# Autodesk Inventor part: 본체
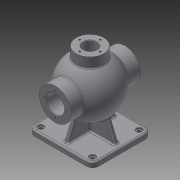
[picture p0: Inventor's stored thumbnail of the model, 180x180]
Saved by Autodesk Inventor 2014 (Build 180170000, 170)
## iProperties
Created: 2015-10
Part Number: 본체
Material: Generic
Document SubType Name: Modeling
Designer: youjin22
Density: 1 g/cm^3
Appearance: Default
Author: youjin22
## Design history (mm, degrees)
sketch "스케치1"
  geometry: L1 (-50.5, 57.5)-(50.5, 57.5); L2 (62.5, 45.5)-(62.5, -45.5); L3 (50.5, -57.5)-(-50.5, -57.5); L4 (-62.5, -45.5)-(-62.5, 45.5); L5 (-62.5, 57.5)-(62.5, -57.5); L6 (62.5, 57.5)-(-62.5, -57.5); A1 r 12 centre (-50.5, 45.5) between (-50.5, 57.5) and (-62.5, 45.5); A2 r 12 centre (50.5, 45.5) between (62.5, 45.5) and (50.5, 57.5); A3 r 12 centre (50.5, -45.5) between (50.5, -57.5) and (62.5, -45.5); A4 r 12 centre (-50.5, -45.5) between (-62.5, -45.5) and (-50.5, -57.5); 1 further point
  constraints: 12 end point, 8 point on circle, 8 point on line, 8 tangent, 4 centre point, 3 equal radius, 2 midpoint, 2 parallel, 1 horizontal, 1 perpendicular
  dimensions: "d0" = 125 distance of L5.end L6.end; "d1" = 115 distance of L6.start L5.end; "d2" = 12 radius of A1
extrude "돌출1" new body sketch "스케치1" distance "d3" = 10; taper "d4" = 0 deg
sketch "스케치2"
  geometry: L1 (0, 32)-(0, 138); A1 r 53 centre (0, 85) between (0, 32) and (0, 138); A2 r 53 centre (0, 85) between (0, 138) and (0, 32); 1 further point
  constraints: 4 point on circle, 2 centre point, 2 end point, 1 vertical, 1 vertical alignment
  dimensions: "d5" = 53 radius of A1; "d6" = 85 distance of A1.centre point (0, 0)
revolve "회전1" stored, may be unused: angle "d7" = 90 deg
sketch "스케치3"
  geometry: L1 (-50.5, 10)-(-62.5, 10) reference; L2 (62.5, 10)-(50.5, 10) reference; L3 (-52.5, 10)-(-37.379, 47.426); L4 (52.5, 10)-(37.379, 47.426); L5 (-62.5, 0)-(-62.5, 10) reference; L6 (62.5, 0)-(62.5, 10) reference; L7 (-52.5, 10)-(52.5, 10); L8 (-37.379, 47.426)-(37.379, 47.426); A1 r 53 centre (0, 85) between (-37.379, 47.426) and (37.379, 47.426) reference; 1 further point
  constraints: 8 end point, 2 point on circle, 2 point on line, 1 perpendicular
  dimensions: "d8" = 10 distance of L3.start L1.end; "d9" = 10 distance of L4.start L2.start; "d10" = 22 deg angle of L3 L5; "d11" = 22 deg angle of L4 L6
extrude "돌출2" join sketch "스케치3" stored distance "d12" = 8; taper "d13" = 0 deg
extrude "돌출10" join sketch "스케치3" stored distance "d96" = 8; taper "d97" = 0 deg
sketch "스케치4"
  geometry: L1 (-45.5, 10)-(-57.5, 10) reference; L2 (57.5, 10)-(45.5, 10) reference; L3 (-47.5, 10)-(-33.719, 44.109); L4 (47.5, 10)-(33.719, 44.109); L5 (57.5, 0)-(57.5, 10) reference; L6 (-57.5, 0)-(-57.5, 10) reference; L7 (-33.719, 44.109)-(33.719, 44.109); A1 r 53 centre (0, 85) between (-33.719, 44.109) and (33.719, 44.109) reference; 1 further point
  constraints: 6 end point, 2 point on circle, 2 point on line
  dimensions: "d14" = 10 distance of L3.start L1.end; "d15" = 10 distance of L4.start L2.start; "d16" = 22 deg angle of L4 L5; "d17" = 22 deg angle of L3 L6
feature "리브1" dims "d18" = 1, "d19" = 8, "d20" = 0, "d21" = 0, "d22" = 1, "d23" = 1
feature "리브2" dims "d24" = 1, "d25" = 8, "d26" = 0, "d27" = 0, "d28" = 1, "d29" = 1
node "작업 평면1"
sketch "스케치5"
  geometry: C1 r 27 at (0, 0); 1 further point
  constraints: 1 centre point, 1 coincident
  dimensions: "d31" = 54 diameter of C1
extrude "돌출3" join sketch "스케치5" stored distance "d32" = 8; taper "d33" = 0 deg
node "작업 평면2"
sketch "스케치6"
  geometry: C1 r 31 at (0, 85); 1 further point
  constraints: 1 centre point, 1 vertical alignment
  dimensions: "d35" = 62 diameter of C1; "d36" = 85 distance of point (0, 0) C1.centre
extrude "돌출4" join sketch "스케치6" distance "d37" = 136; taper "d38" = 0 deg
sketch "스케치7"
  geometry: L1 (0, 128)-(0, 42); A1 r 53 centre (0, 85) between (0, 138) and (0, 32) reference; A2 r 43 centre (0, 85) between (0, 128) and (0, 42); 1 further point
  constraints: 2 end point, 2 point on circle, 2 vertical alignment, 1 centre point, 1 coincident, 1 vertical
  dimensions: "d39" = 43 radius of A2
revolve "회전2" sketch "스케치7" stored, may be unused: angle "d40" = 90 deg
sketch "스케치8"
  geometry: C1 r 27 at (0, 0) reference; C2 r 13 at (0, 0)
  constraints: 1 centre point, 1 coincident
  dimensions: "d41" = 26 diameter of C2
extrude "돌출5" cut sketch "스케치8" stored distance "d42" = 136; taper "d43" = 0 deg
sketch "스케치9"
  geometry: C1 r 31 at (0, 0) reference; C2 r 17.5 at (0, 0); 1 further point
  constraints: 1 centre point, 1 coincident
  dimensions: "d44" = 35 diameter of C2
extrude "돌출6" cut sketch "스케치9" stored distance "d45" = 136; taper "d46" = 0 deg
sketch "스케치10"
  geometry: C1 r 31 at (0, 0) reference; C2 r 17.5 at (0, 0); 1 further point
  constraints: 1 centre point, 1 coincident
  dimensions: "d47" = 35 diameter of C2
extrude "돌출7" cut sketch "스케치10" distance "d48" = 16; taper "d49" = 0 deg
sketch "스케치11"
  geometry: C1 r 17.5 at (0, 0) reference; C2 r 18.5 at (0, 0); 1 further point
  constraints: 1 centre point, 1 coincident
  dimensions: "d50" = 37 diameter of C2
extrude "돌출8" cut sketch "스케치11" distance "d51" = 1.75; taper "d52" = 0 deg
sketch "스케치12"
  geometry: C1 r 18.5 at (0, 0) reference; C2 r 17.5 at (0, 0); 1 further point
  constraints: 1 centre point, 1 coincident
  dimensions: "d53" = 35 diameter of C2
extrude "돌출9" cut sketch "스케치12" stored distance "d54" = 1.75; taper "d55" = 0 deg
sketch "스케치13"
  geometry: C1 r 17.5 at (0, 0) reference; C2 r 31 at (0, 0) reference; A1 r 22.5 centre (0, 0) between (0, -22.5) and (22.5, 0); 3 further points
  constraints: 4 point on circle, 2 horizontal alignment, 2 vertical alignment, 1 centre point, 1 coincident
  dimensions: "d56" = 45 diameter of A1
hole "구멍1" sketch "스케치13" at (0, 22.5), (22.5, 0), (0, -22.5), (-22.5, 0) diameter "d57" = 3.242; stored, may be unused: countersink angle "d61" = 90 deg, drill point angle "d63" = 118 deg; dims "d58" = 12, "d59" = 4, "d60" = 2, "d62" = 15
sketch "스케치14"
  geometry: C1 r 17.5 at (0, 0) reference; C2 r 31 at (0, 0) reference; A1 r 24 centre (0, 0) between (0, -24) and (0, 24); 3 further points
  constraints: 4 point on circle, 2 horizontal alignment, 2 vertical alignment, 1 centre point, 1 coincident
  dimensions: "d64" = 48 diameter of A1
hole "구멍2" sketch "스케치14" at (0, 24), (-24, 0), (0, -24), (24, 0) diameter "d65" = 3.242; stored, may be unused: countersink angle "d69" = 90 deg, drill point angle "d71" = 118 deg; dims "d66" = 16, "d67" = 4, "d68" = 2, "d70" = 19
sketch "스케치15"
  geometry: C1 r 13 at (0, 0) reference; C2 r 27 at (0, 0) reference; A1 r 20 centre (0, 0) between (0, -20) and (-20, 0); 2 further points
  constraints: 4 point on circle, 2 horizontal alignment, 2 vertical alignment, 1 centre point, 1 coincident
  dimensions: "d72" = 40 diameter of A1
hole "구멍3" sketch "스케치15" at (0, 20), (-20, 0), (0, -20), (20, 0) diameter "d73" = 3.242; stored, may be unused: countersink angle "d77" = 90 deg, drill point angle "d79" = 118 deg; dims "d74" = 9, "d75" = 4, "d76" = 2, "d78" = 11
chamfer "모따기1" distance "d80" = 1; stored, may be unused: second distance "d81" = 2, angle "d82" = 45 deg
node "작업 평면3"
sketch "스케치16"
  geometry: L1 (-27, 0)-(27, 0) reference; 2 further points
  constraints: 1 vertical alignment, 1 other
  dimensions: "d83" = 10 distance from line of point (0, -10) L1
feature "엠보싱1" sketch "스케치16" dims "d84" = 0.5, "d85" = 0
sketch "스케치17"
  geometry: A1 r 12 centre (50.5, -45.5) between (50.5, -57.5) and (62.5, -45.5) reference; A2 r 12 centre (50.5, 45.5) between (62.5, 45.5) and (50.5, 57.5) reference; A3 r 12 centre (-50.5, 45.5) between (-50.5, 57.5) and (-62.5, 45.5) reference; A4 r 12 centre (-50.5, -45.5) between (-62.5, -45.5) and (-50.5, -57.5) reference; 5 further points
  constraints: 4 coincident
hole "구멍4" sketch "스케치17" at (-50.5, 45.5), (50.5, 45.5), (50.5, -45.5), (-50.5, -45.5) diameter "d86" = 8; stored, may be unused: countersink angle "d90" = 90 deg, drill point angle "d92" = 0 deg; dims "d87" = 9, "d88" = 12, "d89" = 3, "d91" = 10
fillet "모깎기1" dims "d93" = 3
fillet "모깎기4" dims "d98" = 3
fillet "모깎기5" dims "d99" = 3
fillet "모깎기6" dims "d100" = 3
fillet "모깎기7" dims "d101" = 3
node "솔리드1"
other parameters: "d34" = -68
